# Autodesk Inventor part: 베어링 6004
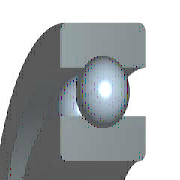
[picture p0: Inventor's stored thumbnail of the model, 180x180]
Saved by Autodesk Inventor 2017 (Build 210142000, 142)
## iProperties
IsCustomPart: 1
Created: 2012-02
Part Number: 베어링 6004
Material: 강철, 연강
Description: 깊은 그루브 볼 베어링
Document SubType Name: Modeling
Standard: KS B 2023
Designer: mduedu
Standards Organization: KS
Language: ko-KR
Size Designation: 6004 - 20 x 42 x 12
Categories: <MemberInstance><Categories><Category DisplayName="샤프트 부품" InternalName="7f7aeb1f-a693-4053-b835-cee3144e0d98" Mnemonic="SHFT"><Category DisplayName="베어링" Inter
Density: 1 g/cm^3
Appearance: 노란색
Author: mduedu
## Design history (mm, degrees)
sketch "스케치" dims "d0" = 5.72 (= -0.26 x WD + 0.26 x BD)
  geometry: L1 (3.14, 15.5)-(8.86, 15.5); L2 (6, 15.5)-(6, 12.64); L3 (6, 15.5)-(6, 18.36); L4 (3.875, 13.586)-(0, 13.586); L5 (0, 10)-(12, 10); L6 (3.875, 17.414)-(0, 17.414); L7 (0, 21)-(12, 21); L8 (12, 10)-(12, 13.586); L9 (8.125, 13.586)-(12, 13.586); L10 (8.125, 17.414)-(12, 17.414); L11 (12, 21)-(12, 17.414); L12 (-1.4, 0)-(8.4, 0) reference; L13 (0, -0.3)-(0, 5.3) reference
  constraints: 22 end point, 4 point on line, 2 collinear, 2 perpendicular, 2 symmetric about line, 1 midpoint, 1 parallel, 14 other
  dimensions: "d9" = 20 diameter of L5 L12 (= WD); "d11" = 42 diameter of L7 L12 (= BD); "d12" = 12 distance between parallel lines of L8 L13 (= KB); "d13" = 27.172 diameter of L9 L12 (= 0.326 x BD + 0.674 x WD)
revolve "본체" stored, may be unused: angle "d6" = 90 deg
revolve "볼" stored, may be unused: angle "d7" = 90 deg
pattern_circular "IDS_ARRAYBALL[SIMPL:T]" dims angle "d3" = 360 deg
body "Solid1"
fillet "모깎기1" dims "d1" = 0.6 (= KRS)
other parameters: "WD" = 20 [user parameter; used in 5 equation terms], "BD" = 42 [user parameter; used in 5 equation terms], "KB" = 12 [user parameter; used in 1 equation term], "KRS" = 0.6 [user parameter; used in 1 equation term], "d4" = 0, "d5" = 0, "d8" = 0, "d14" = 0, "d15" = 0, "BBA" = 0 [user parameter], "BC0" = 5000000 [user parameter], "BC" = 9360000 [user parameter], "BR" = 21 (= 0.5 x BD) [user parameter]
